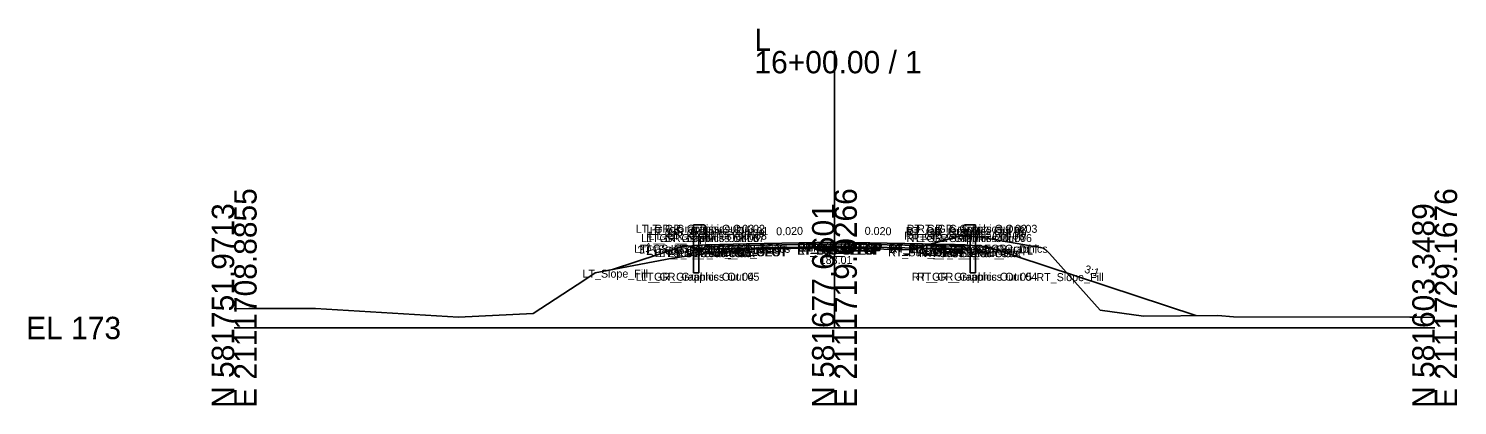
# Model space of a CAD drawing. Extents: x -26 to 3453, y -333 to 9539.
# Drawn here: x -25.7 to 152.8, y 6490.3 to 6537.5 of the extents above; entities that cross this region are included whole.
import ezdxf

# ---------------------------------------------------------------- set-up
doc = ezdxf.new("R2010")
doc.units = 0
for name, color, linetype in [('Default', 7, 'Continuous'), ('Exist Cross Section Cell', 7, 'Continuous'), ('Exist XS Center Line Elevation Label', 7, 'Continuous'), ('Exist XS Ground Line', 7, 'Continuous'), ('Prop CMT Guardrail Graphics', 7, 'Continuous'), ('Prop CMT Pvmt Course 1', 7, 'Continuous'), ('Prop CMT Pvmt Course 2', 7, 'Continuous'), ('Prop CMT Pvmt Course 3', 7, 'Continuous'), ('Prop CMT Pvmt Surface', 7, 'Continuous'), ('Prop CMT Pvmt Surface Shoulder', 7, 'Continuous'), ('Prop CMT Shld Paved Course 1', 7, 'Continuous'), ('Prop CMT Shld Paved Course 2', 7, 'Continuous'), ('Prop CMT Shld Paved Course 3', 7, 'Continuous'), ('Prop CMT Slope Grass', 7, 'Continuous'), ('Prop CMT Subgrade Earthwork', 7, 'Continuous'), ('Prop XS SE Text', 7, 'Continuous'), ('Prop XS Side Slope Text', 7, 'Continuous'), ('Scratch_Level_0', 7, 'Continuous')]:
    doc.layers.add(name, color=color, linetype=linetype)

msp = doc.modelspace()

# ---------------------------------------------------------------- linework, layer by layer
at = {"layer": 'Exist Cross Section Cell'}
for p, q in [((75, 6500), (75, 6534.66)), ((0, 6500), (75, 6500)), ((75, 6500), (150, 6500))]:
    msp.add_line(p, q, dxfattribs=at)
at = {"layer": 'Exist XS Ground Line'}
for p, q in [((84.43, 6509.78), (90.88, 6511.55)), ((90.88, 6511.55), (93.31, 6511.35)), ((93.31, 6511.35), (101.16, 6509.99)), ((57.72, 6509.17), (65.45, 6509.9)), ((65.45, 6509.9), (66.96, 6509.91)), ((66.96, 6509.91), (74.77, 6510.01)), ((74.77, 6510.01), (76.35, 6509.98)), ((76.35, 6509.98), (84.43, 6509.78)), ((101.16, 6509.99), (101.86, 6509.33)), ((101.86, 6509.33), (108.19, 6502.21)), ((45.1, 6506.88), (54.75, 6508.75)), ((54.75, 6508.75), (57.72, 6509.17)), ((37.37, 6501.8), (43.83, 6506.03)), ((43.83, 6506.03), (45.1, 6506.88)), ((0, 6502.38), (1.82, 6502.42)), ((1.82, 6502.42), (10.14, 6502.43)), ((10.14, 6502.43), (28.03, 6501.34)), ((108.19, 6502.21), (113.61, 6501.48)), ((28.03, 6501.34), (37.37, 6501.8)), ((113.61, 6501.48), (122.91, 6501.58)), ((122.91, 6501.58), (124.87, 6501.41)), ((124.87, 6501.41), (146.9, 6501.34)), ((146.9, 6501.34), (147.49, 6501.35)), ((147.49, 6501.35), (148.14, 6501.36)), ((148.14, 6501.36), (148.51, 6501.35)), ((148.51, 6501.35), (150, 6501.31))]:
    msp.add_line(p, q, dxfattribs=at)
at = {"layer": 'Prop CMT Guardrail Graphics'}
for points in [[(57.39, 6506.91), (57.39, 6512.91)], [(57.39, 6512.91), (58.72, 6512.91), (58.99, 6512.62)], [(92.61, 6512.91), (91.28, 6512.91), (91.01, 6512.62)], [(92.61, 6506.91), (92.61, 6512.91)], [(58.99, 6512.04), (58.72, 6511.75), (58.05, 6511.75)], [(58.05, 6511.75), (58.05, 6506.91)], [(58.99, 6512.62), (58.72, 6512.33)], [(58.72, 6512.33), (58.99, 6512.04)], [(91.01, 6512.62), (91.28, 6512.33)], [(91.28, 6512.33), (91.01, 6512.04)], [(91.01, 6512.04), (91.28, 6511.75), (91.95, 6511.75)], [(91.95, 6511.75), (91.95, 6506.91)], [(58.05, 6506.91), (57.39, 6506.91)], [(91.95, 6506.91), (92.61, 6506.91)]]:
    msp.add_lwpolyline(points, dxfattribs=at)
at = {"layer": 'Prop CMT Pvmt Course 1'}
for points in [[(75, 6510.74), (64, 6510.52)], [(64, 6510.31), (75, 6510.53)], [(64, 6510.52), (64, 6510.31)], [(75, 6510.53), (75, 6510.74)], [(75, 6510.74), (86, 6510.52)], [(75, 6510.53), (75, 6510.74)], [(86, 6510.31), (75, 6510.53)], [(86, 6510.52), (86, 6510.31)]]:
    msp.add_lwpolyline(points, dxfattribs=at)
msp.add_lwpolyline([(75, 6510.53), (75, 6510.61), (75, 6510.61), (75, 6510.53)], close=True, dxfattribs=at)
msp.add_lwpolyline([(75, 6510.53), (75, 6510.61), (75, 6510.61), (75, 6510.53)], close=True, dxfattribs=at)
at = {"layer": 'Prop CMT Pvmt Course 2'}
for points in [[(75, 6510.53), (64, 6510.31)], [(64, 6510.31), (64, 6509.97)], [(64, 6509.97), (75, 6510.19)], [(75, 6510.19), (75, 6510.53)], [(75, 6510.19), (75, 6510.53)], [(75, 6510.53), (86, 6510.31)], [(86, 6509.97), (75, 6510.19)], [(86, 6510.31), (86, 6509.97)]]:
    msp.add_lwpolyline(points, dxfattribs=at)
at = {"layer": 'Prop CMT Pvmt Course 3'}
for points in [[(75, 6510.19), (64, 6509.97)], [(64, 6509.97), (75, 6510.19)], [(64, 6509.97), (64, 6509.97)], [(75, 6510.19), (75, 6510.19)], [(75, 6510.19), (86, 6509.97)], [(86, 6509.97), (75, 6510.19)], [(75, 6510.19), (75, 6510.19)], [(86, 6509.97), (86, 6509.97)]]:
    msp.add_lwpolyline(points, dxfattribs=at)
at = {"layer": 'Prop CMT Pvmt Surface'}
for points in [[(75, 6510.74), (64, 6510.52)], [(75, 6510.74), (86, 6510.52)]]:
    msp.add_lwpolyline(points, dxfattribs=at)
at = {"layer": 'Prop CMT Pvmt Surface Shoulder'}
for points in [[(64, 6510.52), (59, 6510.42)], [(86, 6510.52), (91, 6510.42)]]:
    msp.add_lwpolyline(points, dxfattribs=at)
at = {"layer": 'Prop CMT Shld Paved Course 1'}
for points in [[(64, 6510.52), (59, 6510.42), (58.79, 6510.2)], [(58.79, 6510.2), (64, 6510.31)], [(64, 6510.31), (64, 6510.52)], [(86, 6510.52), (91, 6510.42), (91.21, 6510.2)], [(86, 6510.31), (86, 6510.52)], [(91.21, 6510.2), (86, 6510.31)]]:
    msp.add_lwpolyline(points, dxfattribs=at)
at = {"layer": 'Prop CMT Shld Paved Course 2'}
for points in [[(64, 6510.31), (58.79, 6510.2), (58.45, 6509.86)], [(58.45, 6509.86), (64, 6509.97)], [(64, 6509.97), (64, 6510.31)], [(86, 6510.31), (91.21, 6510.2), (91.55, 6509.86)], [(86, 6509.97), (86, 6510.31)], [(91.55, 6509.86), (86, 6509.97)]]:
    msp.add_lwpolyline(points, dxfattribs=at)
at = {"layer": 'Prop CMT Shld Paved Course 3'}
for points in [[(64, 6509.97), (58.45, 6509.86)], [(58.45, 6509.86), (64, 6509.97)], [(58.45, 6509.86), (58.45, 6509.86), (58.45, 6509.86)], [(64, 6509.97), (64, 6509.97)], [(86, 6509.97), (91.55, 6509.86)], [(91.55, 6509.86), (86, 6509.97)], [(86, 6509.97), (86, 6509.97)], [(91.55, 6509.86), (91.55, 6509.86), (91.55, 6509.86)]]:
    msp.add_lwpolyline(points, dxfattribs=at)
at = {"layer": 'Prop CMT Slope Grass'}
for points in [[(56, 6510.18), (47.28, 6507.3)], [(58.99, 6510.41), (56, 6510.18)], [(59, 6510.42), (58.99, 6510.41)], [(91, 6510.42), (91.01, 6510.41)], [(91.01, 6510.41), (94, 6510.18)], [(94, 6510.18), (120.14, 6501.55)]]:
    msp.add_lwpolyline(points, dxfattribs=at)
at = {"layer": 'Prop CMT Subgrade Earthwork'}
for points in [[(58.45, 6509.86), (57.98, 6510.33)], [(64, 6509.97), (58.45, 6509.86)], [(75, 6510.19), (64, 6509.97)], [(75, 6510.19), (86, 6509.97)], [(86, 6509.97), (91.55, 6509.86)], [(91.55, 6509.86), (92.02, 6510.33)]]:
    msp.add_lwpolyline(points, dxfattribs=at)

# ---------------------------------------------------------------- texts
at = {"layer": 'Default'}
msp.add_text('-', height=0.0001, dxfattribs=at).set_placement((0, 6500))
at = {"layer": 'Exist Cross Section Cell'}
for s, p in [('L', (65, 6534.66)), ('16+00.00 / 1', (65, 6531.86)), ('EL 173', (-26, 6498.6))]:
    msp.add_text(s, height=2.8, dxfattribs=at).set_placement(p)
for s, p in [('E 2111708.8855', (2.8, 6490)), ('E 2111719.0266', (77.8, 6490)), ('E 2111729.1676', (152.8, 6490)), ('N 581751.9713', (0, 6490)), ('N 581677.6601', (75, 6490)), ('N 581603.3489', (150, 6490))]:
    msp.add_text(s, height=2.8, rotation=90, dxfattribs=at).set_placement(p)
at = {"layer": 'Exist XS Center Line Elevation Label'}
msp.add_text('183.01', height=1, dxfattribs=at).set_placement((73.16, 6508.01))
at = {"layer": 'Prop XS SE Text'}
for rotation, p in [(1.1458, (67.73, 6511.59)), (358.8542, (78.77, 6511.66))]:
    msp.add_text('0.020', height=1, rotation=rotation, dxfattribs=at).set_placement(p)
at = {"layer": 'Prop XS Side Slope Text'}
for rotation, p in [(18.2629, (50.65, 6509.2)), (341.7371, (106.15, 6506.96))]:
    msp.add_text('3:1', height=1, rotation=rotation, dxfattribs=at).set_placement(p)
at = {"layer": 'Scratch_Level_0'}
for s, p in [('LT_GR_Graphics Out 03', (50.17, 6511.91)), ('LT_GR_Graphics Out 02', (51.52, 6511.91)), ('RT_GR_Graphics Out 02', (84.02, 6511.91)), ('RT_GR_Graphics Out 03', (85.34, 6511.91)), ('LT_GR_Graphics Out 06', (50.83, 6510.75)), ('LT_GR_Graphics Out 07', (51.48, 6510.75)), ('LT_GR_Graphics Out 09', (51.49, 6511.33)), ('LT_GR_Graphics Out 08', (51.76, 6511.04)), ('LT_GR_Graphics Out 01', (51.94, 6511.62)), ('RT_GR_Graphics Out 08', (83.72, 6511.04)), ('RT_GR_Graphics Out 01', (83.9, 6511.62)), ('RT_GR_Graphics Out 07', (83.98, 6510.75)), ('RT_GR_Graphics Out 09', (84, 6511.33)), ('RT_GR_Graphics Out 06', (84.66, 6510.75)), ('LT_GS_OS_GR_Face_Graphics', (49.99, 6509.41)), ('LT_Sub_Trench_Out_DLT', (50.63, 6509.33)), ('LT_GS_OS_CTL', (51.46, 6509.18)), ('LT_Sub_Trench_Out', (52.56, 6508.86)), ('LT_PS3_Shelf_Out', (53.1, 6508.86)), ('LT_PS3_OEOP', (54.23, 6508.86)), ('LT_PS2_OEOP', (54.57, 6509.2)), ('LT_PS1_OEOP', (54.91, 6509.42)), ('LT_PV2_OEOT', (59.75, 6509.31)), ('LT_PV3_OEOT', (59.75, 6508.97)), ('LT_Sub_OEOT', (59.77, 6508.97)), ('LT_PV1_OEOT', (59.87, 6509.52)), ('RT_PV2_OEEOP', (70.33, 6509.53)), ('RT_PV3_OEEOP', (70.33, 6509.19)), ('RT_Sub_OEEOP', (70.36, 6509.19)), ('LT_PV2_OEEOP', (70.39, 6509.53)), ('LT_PV3_OEEOP', (70.39, 6509.19)), ('LT_Sub_OEEOP', (70.42, 6509.19)), ('RT_PV1_OEEOP', (70.45, 6509.61)), ('LT_PV1_OEEOP', (70.51, 6509.61)), ('RT_PV2_IEEOP', (70.71, 6509.53)), ('LT_PV2_IEEOP', (70.77, 6509.53)), ('RT_PV1_IEEOP', (70.83, 6509.61)), ('LT_PV1_IEEOP', (70.89, 6509.61)), ('PV2_PGL', (72.35, 6509.53)), ('PV1_PGL', (72.47, 6509.74)), ('RT_PV2_OEOT', (81.69, 6509.31)), ('RT_PV3_OEOT', (81.69, 6508.97)), ('RT_Sub_OEOT', (81.71, 6508.97)), ('RT_PV1_OEOT', (81.81, 6509.52)), ('RT_GS_OS_GR_Face_Graphics', (81.95, 6509.41)), ('RT_Sub_Trench_Out_DLT', (84.61, 6509.33)), ('RT_Sub_Trench_Out', (85.6, 6508.86)), ('RT_PS3_Shelf_Out', (86.15, 6508.86)), ('RT_PS1_OEOP', (86.85, 6509.42)), ('RT_PS2_OEOP', (86.94, 6509.2)), ('RT_PS3_OEOP', (87.28, 6508.86)), ('RT_GS_OS_CTL', (89.4, 6509.18)), ('LT_Slope_Fill', (43.52, 6506.3)), ('LT_GR_Graphics Out 04', (50.16, 6505.91)), ('LT_GR_Graphics Out 05', (50.83, 6505.91)), ('RT_GR_Graphics Out 05', (84.67, 6505.91)), ('RT_GR_Graphics Out 04', (85.32, 6505.91)), ('RT_Slope_Fill', (100.24, 6505.86))]:
    msp.add_text(s, height=1, dxfattribs=at).set_placement(p)

doc.saveas('drawing.dxf')
